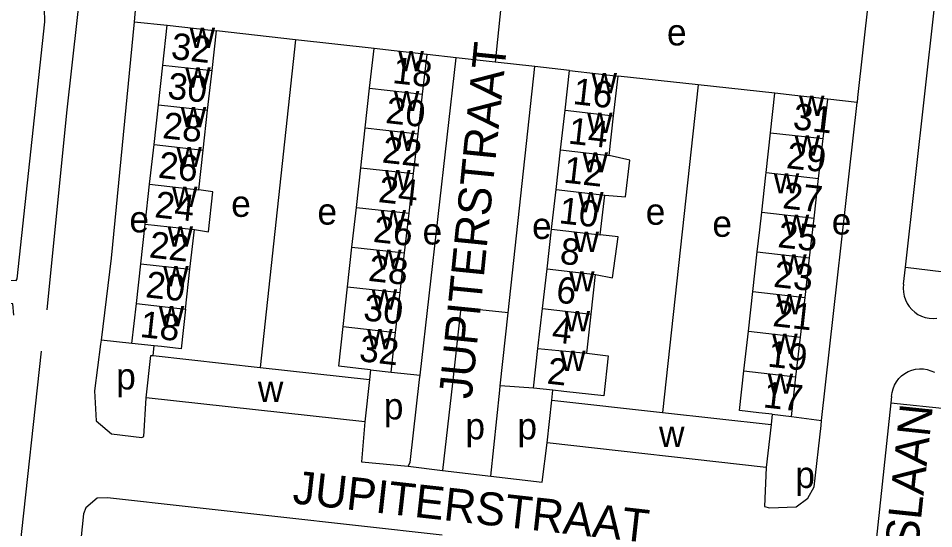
# Model space of a CAD drawing. Extents: x 161936 to 163647, y 386450 to 388633.
# Drawn here: x 162059.5 to 162198.4, y 386640.9 to 386718.3 of the extents above; entities that cross this region are included whole.
import ezdxf

# ---------------------------------------------------------------- set-up
doc = ezdxf.new("R2010")
doc.units = 0
for name, color, linetype in [('BLT_Basislijn', 7, 'Continuous'), ('BLT_Bebouwing', 7, 'Continuous'), ('BLT_Centroide', 7, 'Continuous'), ('BLT_Huisnummer', 7, 'Continuous'), ('BLT_Huisnummer_ tussenligend', 7, 'Continuous'), ('BLT_Onderverdeling_panden', 7, 'Continuous'), ('BLT_Straatnaam', 7, 'Continuous')]:
    doc.layers.add(name, color=color, linetype=linetype)

msp = doc.modelspace()

# ---------------------------------------------------------------- linework, layer by layer
at = {"layer": 'BLT_Basislijn'}
for p, q in [((162194.17, 386680.56), (162198.58, 386720.02)), ((162077.13, 386717.8), (162082.14, 386717.27)), ((162101.6, 386715.09), (162089.61, 386716.44)), ((162101.6, 386715.09), (162096.27, 386665.35)), ((162113.53, 386713.74), (162101.6, 386715.09)), ((162125.99, 386712.34), (162121.57, 386712.84)), ((162120.52, 386664.18), (162125.99, 386712.34)), ((162131.92, 386711.68), (162125.99, 386712.34)), ((162137.92, 386711), (162131.92, 386711.68)), ((162133.88, 386673.63), (162137.92, 386711)), ((162143.19, 386710.41), (162137.92, 386711)), ((162162.72, 386708.24), (162150.57, 386709.57)), ((162162.72, 386708.24), (162157.31, 386658.51)), ((162174.32, 386706.98), (162162.72, 386708.24)), ((162186.81, 386705.55), (162182.36, 386706.08)), ((162181.43, 386657.28), (162186.81, 386705.55)), ((162193.88, 386677.96), (162194.17, 386680.56)), ((162194.17, 386680.56), (162203.05, 386679.46)), ((162132.68, 386662.57), (162133.88, 386673.63)), ((162076.8, 386669), (162072.1, 386669.48)), ((162079.99, 386667.13), (162080.16, 386668.63)), ((162063, 386667.82), (162056.98, 386612.23)), ((162113, 386664.99), (162112.84, 386663.53)), ((162116.12, 386664.64), (162120.52, 386664.18)), ((162137.72, 386662.22), (162132.68, 386662.57)), ((162140.49, 386660.38), (162140.64, 386661.89)), ((162192.05, 386660.94), (162191.95, 386659.97)), ((162191.95, 386659.97), (162189.19, 386634.34)), ((162191.95, 386659.97), (162200.69, 386659.08)), ((162173.92, 386658.23), (162173.76, 386656.67)), ((162176.85, 386657.91), (162181.43, 386657.28)), ((162118.68, 386650.35), (162123.89, 386649.71)), ((162123.89, 386649.71), (162131.27, 386648.82))]:
    msp.add_line(p, q, dxfattribs=at)
for points in [[(162063.93, 386674.11), (162066.91, 386704.01), (162076.72, 386791.75), (162076.05, 386797.16), (162075.44, 386799.23), (162073.83, 386800.75), (162073.04, 386800.97)], [(162134.7, 386740.02), (162092.95, 386744.8), (162083.32, 386745.32), (162082.31, 386745.05), (162079.58, 386742.51), (162079.26, 386741.13), (162077.24, 386718.96), (162077.13, 386717.8)], [(162134.7, 386740.02), (162185.78, 386734.22), (162188.22, 386732.88), (162189.33, 386731.05), (162189.39, 386729), (162186.89, 386706.3), (162186.81, 386705.55)], [(162134.15, 386733.68), (162133.46, 386726.98), (162131.92, 386711.68)], [(162058.89, 386673.28), (162058.73, 386675), (162055.17, 386675.25), (162055.23, 386677.48), (162055.56, 386678.72), (162059.24, 386678.55), (162059.4, 386678.8), (162063.55, 386717.82), (162063.51, 386719.81), (162058.31, 386720.58)], [(162077.13, 386717.8), (162073.66, 386681.91), (162072.1, 386669.48)], [(162193.88, 386677.96), (162193.82, 386677.37), (162193.85, 386676.77), (162193.95, 386676.18), (162194.14, 386675.61), (162194.4, 386675.07), (162194.72, 386674.57), (162195.11, 386674.12), (162195.56, 386673.72), (162196.06, 386673.39), (162196.59, 386673.12), (162197.16, 386672.93), (162197.75, 386672.82), (162198.35, 386672.78), (162198.94, 386672.83)], [(162133.88, 386673.63), (162126.71, 386674.41), (162125.41, 386662.96), (162123.89, 386649.71)], [(162072.1, 386669.48), (162072.02, 386668.85), (162071.09, 386661.81), (162071.34, 386657.25), (162073.69, 386655.26), (162078.31, 386654.69), (162078.62, 386654.88), (162078.95, 386660.72)], [(162192.05, 386660.94), (162192.12, 386661.53), (162192.27, 386662.1), (162192.49, 386662.65), (162192.78, 386663.17), (162193.14, 386663.64), (162193.56, 386664.06), (162194.04, 386664.42), (162194.55, 386664.71), (162195.11, 386664.93), (162195.68, 386665.07), (162196.27, 386665.14), (162196.87, 386665.12), (162197.45, 386665.03), (162198.02, 386664.85), (162198.56, 386664.61)], [(162118.68, 386650.35), (162119, 386650.92), (162120.44, 386663.53), (162120.52, 386664.18)], [(162131.27, 386648.82), (162132.6, 386661.89), (162132.68, 386662.57)], [(162173.04, 386650.17), (162172.75, 386644.22), (162173.54, 386644.01), (162177.55, 386644.17), (162179.34, 386645.51), (162180.29, 386647.2), (162181.35, 386656.55), (162181.43, 386657.28)], [(162112.13, 386657.08), (162111.62, 386651.03), (162118.68, 386650.35)], [(162131.27, 386648.82), (162139.01, 386647.94), (162139.77, 386653.88)], [(162123.87, 386639.9), (162073.06, 386645.54), (162071.51, 386645.5), (162069.82, 386644.03), (162069.43, 386643.12), (162066.97, 386618.97), (162066.86, 386617.91)]]:
    msp.add_lwpolyline(points, dxfattribs=at)
at = {"layer": 'BLT_Bebouwing'}
for p, q in [((162081.47, 386711.24), (162082.14, 386717.27)), ((162088.94, 386710.41), (162089.61, 386716.44)), ((162112.86, 386707.71), (162113.53, 386713.74)), ((162120.89, 386706.82), (162121.57, 386712.84)), ((162080.8, 386705.2), (162081.47, 386711.24)), ((162088.27, 386704.38), (162088.94, 386710.41)), ((162142.5, 386704.38), (162143.19, 386710.41)), ((162149.88, 386703.55), (162150.57, 386709.57)), ((162112.19, 386701.69), (162112.86, 386707.71)), ((162120.21, 386700.8), (162120.89, 386706.82)), ((162173.66, 386700.96), (162174.32, 386706.98)), ((162181.67, 386700.07), (162182.36, 386706.08)), ((162080.14, 386699.17), (162080.8, 386705.2)), ((162087.6, 386698.34), (162088.27, 386704.38)), ((162141.82, 386698.36), (162142.5, 386704.38)), ((162149.2, 386697.52), (162149.88, 386703.55)), ((162111.52, 386695.66), (162112.19, 386701.69)), ((162119.52, 386694.77), (162120.21, 386700.8)), ((162173, 386694.93), (162173.66, 386700.96)), ((162079.47, 386693.14), (162080.14, 386699.17)), ((162180.98, 386694.04), (162181.67, 386700.07)), ((162086.94, 386692.31), (162087.6, 386698.34)), ((162141.14, 386692.34), (162141.82, 386698.36)), ((162110.85, 386689.64), (162111.52, 386695.66)), ((162118.84, 386688.75), (162119.52, 386694.77)), ((162180.29, 386688.02), (162180.98, 386694.04)), ((162078.8, 386687.1), (162079.47, 386693.14)), ((162140.46, 386686.31), (162141.14, 386692.34)), ((162147.84, 386685.48), (162148.52, 386691.5)), ((162110.18, 386683.61), (162110.85, 386689.64)), ((162118.16, 386682.72), (162118.84, 386688.75)), ((162179.61, 386682), (162180.29, 386688.02)), ((162078.13, 386681.07), (162078.8, 386687.1)), ((162085.6, 386680.24), (162086.27, 386686.28)), ((162139.77, 386680.29), (162140.46, 386686.31)), ((162109.51, 386677.58), (162110.18, 386683.61)), ((162117.48, 386676.7), (162118.16, 386682.72)), ((162170.99, 386676.86), (162171.67, 386682.88)), ((162077.46, 386675.04), (162078.13, 386681.07)), ((162178.92, 386675.98), (162179.61, 386682)), ((162084.93, 386674.21), (162085.6, 386680.24)), ((162139.09, 386674.27), (162139.77, 386680.29)), ((162146.47, 386673.43), (162147.15, 386679.45)), ((162108.84, 386671.56), (162109.51, 386677.58)), ((162170.32, 386670.84), (162170.99, 386676.86)), ((162116.8, 386670.67), (162117.48, 386676.7)), ((162178.23, 386669.96), (162178.92, 386675.98)), ((162076.8, 386669), (162077.46, 386675.04)), ((162138.4, 386668.24), (162139.09, 386674.27)), ((162145.8, 386667.5), (162146.47, 386673.43)), ((162116.12, 386664.64), (162116.8, 386670.67)), ((162169.64, 386664.81), (162170.32, 386670.84)), ((162177.54, 386663.93), (162178.23, 386669.96)), ((162080.16, 386668.63), (162076.8, 386669)), ((162079.99, 386667.13), (162096.27, 386665.35)), ((162137.72, 386662.22), (162138.4, 386668.24)), ((162096.27, 386665.35), (162112.84, 386663.53)), ((162113, 386664.99), (162116.12, 386664.64)), ((162112.84, 386663.53), (162112.13, 386657.08)), ((162176.85, 386657.91), (162177.54, 386663.93)), ((162140.64, 386661.89), (162137.72, 386662.22)), ((162112.13, 386657.08), (162078.95, 386660.72)), ((162139.77, 386653.88), (162140.49, 386660.38)), ((162140.49, 386660.38), (162157.31, 386658.51)), ((162157.31, 386658.51), (162173.76, 386656.67)), ((162173.92, 386658.23), (162176.85, 386657.91)), ((162173.76, 386656.67), (162173.04, 386650.17)), ((162173.04, 386650.17), (162139.77, 386653.88))]:
    msp.add_line(p, q, dxfattribs=at)
for points in [[(162082.14, 386717.27), (162086.57, 386716.78), (162089.61, 386716.44)], [(162121.57, 386712.84), (162116.6, 386713.4), (162113.53, 386713.74)], [(162143.19, 386710.41), (162147.57, 386709.91), (162150.57, 386709.57)], [(162182.36, 386706.08), (162177.39, 386706.64), (162174.32, 386706.98)], [(162148.52, 386691.5), (162151.68, 386691.23), (162152.32, 386696.8), (162149.2, 386697.52)], [(162172.34, 386688.91), (162172.95, 386694.52), (162173, 386694.93)], [(162086.27, 386686.28), (162088.41, 386685.93), (162089.08, 386691.98), (162086.94, 386692.31)], [(162171.67, 386682.88), (162172.04, 386686.23), (162172.34, 386688.91)], [(162147.15, 386679.45), (162149.73, 386678.94), (162150.59, 386685.17), (162147.84, 386685.48)], [(162084.93, 386674.21), (162084.27, 386668.18), (162081.27, 386668.51), (162080.16, 386668.63)], [(162113, 386664.99), (162111.15, 386665.2), (162108.17, 386665.53), (162108.84, 386671.56)], [(162078.95, 386660.72), (162079.66, 386667.17), (162079.99, 386667.13)], [(162145.8, 386667.5), (162149.07, 386667.12), (162148.38, 386661.01), (162142.31, 386661.7), (162140.64, 386661.89)], [(162173.92, 386658.23), (162171.89, 386658.46), (162168.96, 386658.79), (162169.64, 386664.81)]]:
    msp.add_lwpolyline(points, dxfattribs=at)
at = {"layer": 'BLT_Onderverdeling_panden'}
for p, q in [((162081.47, 386711.24), (162088.94, 386710.41)), ((162112.86, 386707.71), (162120.89, 386706.82)), ((162080.8, 386705.2), (162088.27, 386704.38)), ((162142.5, 386704.38), (162149.88, 386703.55)), ((162112.19, 386701.69), (162120.21, 386700.8)), ((162173.66, 386700.96), (162181.67, 386700.07)), ((162080.14, 386699.17), (162087.6, 386698.34)), ((162141.82, 386698.36), (162149.2, 386697.52)), ((162111.52, 386695.66), (162119.52, 386694.77)), ((162173, 386694.93), (162180.98, 386694.04)), ((162079.47, 386693.14), (162086.94, 386692.31)), ((162141.14, 386692.34), (162148.52, 386691.5)), ((162110.85, 386689.64), (162118.84, 386688.75)), ((162172.34, 386688.91), (162180.29, 386688.02)), ((162078.8, 386687.1), (162086.27, 386686.28)), ((162140.46, 386686.31), (162147.84, 386685.48)), ((162110.18, 386683.61), (162118.16, 386682.72)), ((162171.67, 386682.88), (162179.61, 386682)), ((162078.13, 386681.07), (162085.6, 386680.24)), ((162139.77, 386680.29), (162147.15, 386679.45)), ((162109.51, 386677.58), (162117.48, 386676.7)), ((162170.99, 386676.86), (162178.92, 386675.98)), ((162077.46, 386675.04), (162084.93, 386674.21)), ((162139.09, 386674.27), (162146.47, 386673.43)), ((162108.84, 386671.56), (162116.8, 386670.67)), ((162170.32, 386670.84), (162178.23, 386669.96)), ((162138.4, 386668.24), (162145.8, 386667.5)), ((162169.64, 386664.81), (162177.54, 386663.93))]:
    msp.add_line(p, q, dxfattribs=at)

# ---------------------------------------------------------------- texts
at = {"layer": 'BLT_Centroide'}
for s, p in [('e', (162157.97, 386714.22)), ('w', (162085.54, 386713.84)), ('w', (162117.21, 386710.28)), ('w', (162084.88, 386707.81)), ('w', (162146.53, 386706.97)), ('w', (162116.53, 386704.25)), ('w', (162178, 386703.53)), ('w', (162084.2, 386701.78)), ('w', (162145.85, 386700.94)), ('w', (162115.87, 386698.22)), ('w', (162177.33, 386697.5)), ('w', (162083.53, 386695.75)), ('w', (162145.17, 386694.94)), ('w', (162115.19, 386692.22)), ('w', (162174.17, 386691.75)), ('w', (162082.87, 386689.72)), ('e', (162091.85, 386688.2)), ('w', (162144.48, 386688.91)), ('e', (162104.94, 386687.02)), ('w', (162114.51, 386686.19)), ('e', (162154.75, 386687)), ('e', (162076.41, 386685.84)), ('e', (162137.5, 386684.84)), ('e', (162164.86, 386685.17)), ('w', (162175.68, 386685.44)), ('e', (162182.98, 386685.51)), ('w', (162082.2, 386683.69)), ('e', (162120.89, 386684)), ('w', (162143.8, 386682.88)), ('w', (162113.84, 386680.16)), ('w', (162175.3, 386679.44)), ('w', (162081.53, 386677.66)), ('w', (162143.12, 386676.88)), ('w', (162113.16, 386674.12)), ('w', (162174.62, 386673.41)), ('w', (162080.86, 386671.59)), ('w', (162142.44, 386670.84)), ('w', (162112.48, 386668.09)), ('w', (162173.93, 386667.38)), ('w', (162141.76, 386664.81)), ('p', (162074.4, 386662)), ('w', (162173.25, 386661.34)), ('w', (162095.9, 386660.12)), ('p', (162115.01, 386657.46)), ('p', (162127.39, 386654.43)), ('p', (162135.28, 386654.43)), ('w', (162156.77, 386653.28)), ('p', (162177.44, 386647.05))]:
    msp.add_text(s, height=4, dxfattribs=at).set_placement(p)
at = {"layer": 'BLT_Huisnummer'}
for s, rotation, p in [('32', 353.6868, (162082.6, 386712.19)), ('18', 353.6559, (162116.21, 386708.52)), ('16', 353.5303, (162143.58, 386705.34)), ('31', 353.6512, (162176.95, 386701.52)), ('22', 353.6527, (162114.64, 386696.46)), ('26', 353.6859, (162080.66, 386694.16)), ('10', 353.5303, (162141.46, 386687.25)), ('26', 353.6496, (162113.28, 386684.41)), ('25', 353.6511, (162174.66, 386683.61)), ('22', 353.6842, (162079.29, 386682.05)), ('6', 353.5312, (162141.03, 386675.21)), ('21', 353.6511, (162173.9, 386671.63)), ('18', 353.6809, (162077.9, 386669.98)), ('32', 353.6383, (162111.15, 386666.31)), ('2', 353.5293, (162139.65, 386662.91)), ('17', 353.6039, (162172.45, 386659.3))]:
    msp.add_text(s, height=4, rotation=rotation, dxfattribs=at).set_placement(p)
at = {"layer": 'BLT_Huisnummer_ tussenligend'}
for s, rotation, p in [('30', 353.6859, (162082.07, 386706.16)), ('20', 353.6559, (162115.16, 386702.46)), ('28', 353.6859, (162081.32, 386700.16)), ('14', 353.5303, (162142.87, 386699.34)), ('29', 353.6511, (162175.97, 386695.61)), ('12', 353.5303, (162142.13, 386693.43)), ('24', 353.6527, (162114.06, 386690.46)), ('27', 353.6511, (162175.4, 386689.52)), ('24', 353.6842, (162080.12, 386688.15)), ('8', 353.5312, (162141.6, 386681.11)), ('28', 353.6496, (162112.54, 386678.5)), ('23', 353.6511, (162174.02, 386677.59)), ('20', 353.6809, (162078.73, 386676.01)), ('30', 353.6496, (162111.79, 386672.51)), ('4', 353.5293, (162140.39, 386669.2)), ('19', 353.6039, (162173.12, 386665.49))]:
    msp.add_text(s, height=4, rotation=rotation, dxfattribs=at).set_placement(p)
at = {"layer": 'BLT_Straatnaam'}
for s, rotation, p in [('JUPITERSTRAAT', 84.2866, (162128.32, 386660.45)), ('MERCURIUSLAAN', 84.0105, (162192.28, 386601.85)), ('JUPITERSTRAAT', 353.6338, (162101.05, 386644.73))]:
    msp.add_text(s, height=5, rotation=rotation, dxfattribs=at).set_placement(p)

doc.saveas('drawing.dxf')
